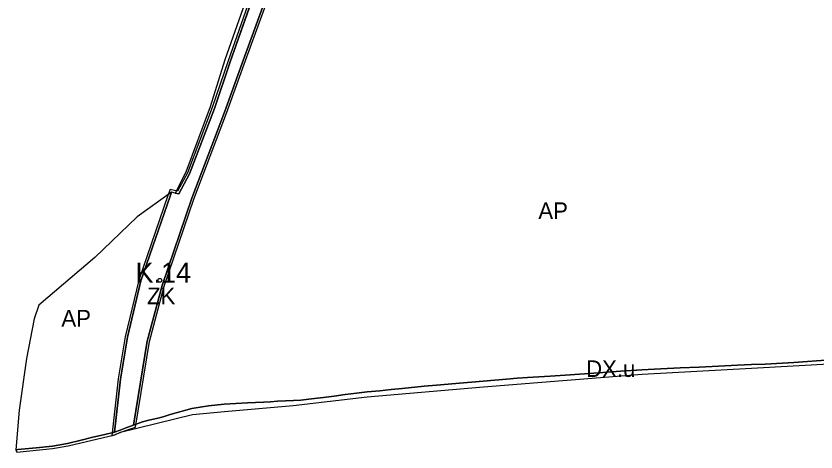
# Model space of a CAD drawing. Extents: x -555509 to -553005, y -1186756 to -1182560.
# Drawn here: x -555509 to -554833, y -1186742 to -1186374 of the extents above; entities that cross this region are included whole.
import ezdxf

# ---------------------------------------------------------------- set-up
doc = ezdxf.new("R2010")
doc.units = 0
for name, color, linetype in [('Level 26', 7, 'Continuous'), ('Level 46', 7, 'Continuous'), ('Level 56', 7, 'Continuous'), ('Level 59', 7, 'Continuous'), ('Level 63', 7, 'Continuous'), ('navrh_ZK', 7, 'Continuous'), ('OBRYS_PLOCH', 7, 'Continuous'), ('stav_AP', 7, 'Continuous'), ('stav_ZK', 7, 'Continuous')]:
    doc.layers.add(name, color=color, linetype=linetype)

msp = doc.modelspace()

# ---------------------------------------------------------------- linework, layer by layer
at = {"layer": 'Level 26'}
for p, q in [((-554821.37, -1186664.53), (-554852.05, -1186666.72)), ((-554964.32, -1186672), (-554980.48, -1186672.71)), ((-554980.05, -1186676.42), (-554887.97, -1186671.38)), ((-554948.16, -1186671.3), (-554964.32, -1186672)), ((-554931.94, -1186670.47), (-554948.16, -1186671.3)), ((-554915.74, -1186669.71), (-554931.94, -1186670.47)), ((-554899.7, -1186668.99), (-554915.74, -1186669.71)), ((-554888, -1186668.27), (-554899.7, -1186668.99)), ((-554876.21, -1186667.95), (-554888, -1186668.27)), ((-554887.97, -1186671.38), (-554789.24, -1186666.07)), ((-554852.05, -1186666.72), (-554876.21, -1186667.95)), ((-555114.15, -1186687.17), (-554980.05, -1186676.42)), ((-555067.42, -1186678.67), (-555076.94, -1186679.25)), ((-555057.9, -1186678.08), (-555067.42, -1186678.67)), ((-555049.48, -1186677.57), (-555057.9, -1186678.08)), ((-555041.02, -1186677.02), (-555049.48, -1186677.57)), ((-555020.94, -1186675.71), (-555041.02, -1186677.02)), ((-555009.68, -1186674.81), (-555020.94, -1186675.71)), ((-554998.42, -1186674.02), (-555009.68, -1186674.81)), ((-554989.46, -1186673.38), (-554998.42, -1186674.02)), ((-554980.48, -1186672.71), (-554989.46, -1186673.38)), ((-555153.89, -1186685.76), (-555164.16, -1186686.63)), ((-555144.04, -1186684.95), (-555153.89, -1186685.76)), ((-555134.47, -1186684.09), (-555144.04, -1186684.95)), ((-555124.31, -1186683.29), (-555134.47, -1186684.09)), ((-555114.3, -1186682.43), (-555124.31, -1186683.29)), ((-555104.56, -1186681.62), (-555114.3, -1186682.43)), ((-555094.73, -1186680.71), (-555104.56, -1186681.62)), ((-555085.82, -1186679.98), (-555094.73, -1186680.71)), ((-555076.94, -1186679.25), (-555085.82, -1186679.98)), ((-555221.37, -1186692.63), (-555230.77, -1186693.78)), ((-555212.22, -1186691.51), (-555221.37, -1186692.63)), ((-555212.22, -1186695.72), (-555114.15, -1186687.17)), ((-555201.78, -1186690.46), (-555212.22, -1186691.51)), ((-555192.13, -1186689.51), (-555201.78, -1186690.46)), ((-555182.72, -1186688.55), (-555192.13, -1186689.51)), ((-555164.16, -1186686.63), (-555182.72, -1186688.55)), ((-555287.89, -1186699.41), (-555293.8, -1186699.81)), ((-555274.43, -1186698.75), (-555287.89, -1186699.41)), ((-555274.79, -1186703.08), (-555212.22, -1186695.72)), ((-555268.4, -1186698.44), (-555274.43, -1186698.75)), ((-555259.21, -1186697.4), (-555268.4, -1186698.44)), ((-555249.31, -1186696.1), (-555259.21, -1186697.4)), ((-555240.22, -1186694.96), (-555249.31, -1186696.1)), ((-555230.77, -1186693.78), (-555240.22, -1186694.96)), ((-555360.21, -1186705.63), (-555378.64, -1186710.67)), ((-555346.28, -1186703.12), (-555360.21, -1186705.63)), ((-555333.11, -1186701.97), (-555346.28, -1186703.12)), ((-555313.32, -1186700.71), (-555333.11, -1186701.97)), ((-555332.83, -1186708.02), (-555274.79, -1186703.08)), ((-555299.97, -1186700.15), (-555313.32, -1186700.71)), ((-555293.8, -1186699.81), (-555299.97, -1186700.15)), ((-555420.67, -1186725.59), (-555359.65, -1186710.58)), ((-555382.98, -1186711.99), (-555387.77, -1186713.28)), ((-555378.64, -1186710.67), (-555382.98, -1186711.99)), ((-555359.65, -1186710.58), (-555332.83, -1186708.02)), ((-555409.6, -1186719.66), (-555415.22, -1186721.67)), ((-555401.91, -1186716.89), (-555409.6, -1186719.66)), ((-555396.64, -1186715.38), (-555401.91, -1186716.89)), ((-555387.77, -1186713.28), (-555396.64, -1186715.38)), ((-555425.54, -1186725.43), (-555434.79, -1186727.67)), ((-555420.84, -1186723.67), (-555425.54, -1186725.43)), ((-555425.26, -1186727.65), (-555420.67, -1186725.59)), ((-555415.22, -1186721.67), (-555420.84, -1186723.67)), ((-555453.9, -1186732.33), (-555465.17, -1186734.97)), ((-555464.81, -1186736.96), (-555425.26, -1186727.65)), ((-555443.89, -1186729.83), (-555453.9, -1186732.33)), ((-555434.79, -1186727.67), (-555443.89, -1186729.83)), ((-555508.02, -1186742.24), (-555477.93, -1186739.2)), ((-555491.66, -1186738.63), (-555507.27, -1186740.17)), ((-555477.98, -1186737.17), (-555491.66, -1186738.63)), ((-555465.17, -1186734.97), (-555477.98, -1186737.17)), ((-555477.93, -1186739.2), (-555464.81, -1186736.96)), ((-555507.27, -1186740.17), (-555508.78, -1186740.27)), ((-555508.78, -1186740.27), (-555508.02, -1186742.24))]:
    msp.add_line(p, q, dxfattribs=at)
at = {"layer": 'Level 46'}
msp.add_circle((-555387.38, -1186597.24), 1.64, dxfattribs=at)
at = {"layer": 'Level 56'}
msp.add_lwpolyline([(-555294.24, -1186306.8), (-555307.65, -1186349.22), (-555329.75, -1186411.97), (-555343.2, -1186451.41), (-555364.14, -1186506.51), (-555372.32, -1186521.97), (-555378.67, -1186520.61), (-555380.64, -1186525.52), (-555405.22, -1186597.12), (-555416.59, -1186645), (-555422.51, -1186680.5), (-555427.89, -1186728.45), (-555420.15, -1186725.55), (-555414.55, -1186723.55), (-555407.81, -1186721.15), (-555396.12, -1186649.06), (-555383.61, -1186602.23), (-555358.59, -1186528.67), (-555330.99, -1186456.07), (-555316.07, -1186414.65), (-555278.64, -1186312.12)], close=True, dxfattribs=at)
at = {"layer": 'navrh_ZK'}
for p, q in [((-555305.75, -1186349.85), (-555327.86, -1186412.63)), ((-555327.86, -1186412.63), (-555341.32, -1186452.09)), ((-555341.32, -1186452.09), (-555362.31, -1186507.34)), ((-555362.31, -1186507.34), (-555371.26, -1186524.24)), ((-555371.26, -1186524.24), (-555374.35, -1186523.58)), ((-555415.22, -1186721.67), (-555409.6, -1186719.66)), ((-555420.84, -1186723.67), (-555415.22, -1186721.67))]:
    msp.add_line(p, q, dxfattribs=at)
for points in [[(-555409.6, -1186719.66), (-555398.08, -1186648.64), (-555385.52, -1186601.65), (-555360.47, -1186527.99), (-555332.87, -1186455.38), (-555317.95, -1186413.97), (-555281.22, -1186313.35)], [(-555374.35, -1186523.58), (-555377.44, -1186522.92), (-555378.76, -1186526.22), (-555403.3, -1186597.68)], [(-555403.3, -1186597.68), (-555414.63, -1186645.4), (-555420.53, -1186680.78), (-555425.54, -1186725.43), (-555420.84, -1186723.67)]]:
    msp.add_lwpolyline(points, dxfattribs=at)
at = {"layer": 'OBRYS_PLOCH'}
for p, q in [((-555281.22, -1186313.35), (-555317.95, -1186413.97)), ((-555310.66, -1186348.84), (-555332.46, -1186411.11)), ((-555327.86, -1186412.63), (-555305.75, -1186349.85)), ((-555305.75, -1186349.85), (-555327.86, -1186412.63)), ((-555332.46, -1186411.11), (-555344.77, -1186450.74)), ((-555341.32, -1186452.09), (-555327.86, -1186412.63)), ((-555327.86, -1186412.63), (-555341.32, -1186452.09)), ((-555317.95, -1186413.97), (-555332.87, -1186455.38)), ((-555344.77, -1186450.74), (-555365.28, -1186506.04)), ((-555362.31, -1186507.34), (-555341.32, -1186452.09)), ((-555341.32, -1186452.09), (-555362.31, -1186507.34)), ((-555332.87, -1186455.38), (-555360.47, -1186527.99)), ((-555365.28, -1186506.04), (-555374.35, -1186523.58)), ((-555371.26, -1186524.24), (-555362.31, -1186507.34)), ((-555362.31, -1186507.34), (-555371.26, -1186524.24)), ((-555374.35, -1186523.58), (-555371.26, -1186524.24)), ((-555371.26, -1186524.24), (-555374.35, -1186523.58)), ((-555360.47, -1186527.99), (-555385.52, -1186601.65)), ((-555385.52, -1186601.65), (-555398.08, -1186648.64)), ((-555398.08, -1186648.64), (-555409.6, -1186719.66)), ((-554852.05, -1186666.72), (-554821.37, -1186664.53)), ((-554821.37, -1186664.53), (-554852.05, -1186666.72)), ((-554980.48, -1186672.71), (-554964.32, -1186672)), ((-554964.32, -1186672), (-554980.48, -1186672.71)), ((-554980.05, -1186676.42), (-554887.97, -1186671.38)), ((-554964.32, -1186672), (-554948.16, -1186671.3)), ((-554948.16, -1186671.3), (-554964.32, -1186672)), ((-554948.16, -1186671.3), (-554931.94, -1186670.47)), ((-554931.94, -1186670.47), (-554948.16, -1186671.3)), ((-554931.94, -1186670.47), (-554915.74, -1186669.71)), ((-554915.74, -1186669.71), (-554931.94, -1186670.47)), ((-554915.74, -1186669.71), (-554899.7, -1186668.99)), ((-554899.7, -1186668.99), (-554915.74, -1186669.71)), ((-554899.7, -1186668.99), (-554888, -1186668.27)), ((-554888, -1186668.27), (-554899.7, -1186668.99)), ((-554888, -1186668.27), (-554876.21, -1186667.95)), ((-554876.21, -1186667.95), (-554888, -1186668.27)), ((-554887.97, -1186671.38), (-554789.24, -1186666.07)), ((-554876.21, -1186667.95), (-554852.05, -1186666.72)), ((-554852.05, -1186666.72), (-554876.21, -1186667.95)), ((-555114.15, -1186687.17), (-554980.05, -1186676.42)), ((-555076.94, -1186679.25), (-555067.42, -1186678.67)), ((-555067.42, -1186678.67), (-555076.94, -1186679.25)), ((-555067.42, -1186678.67), (-555057.9, -1186678.08)), ((-555057.9, -1186678.08), (-555067.42, -1186678.67)), ((-555057.9, -1186678.08), (-555049.48, -1186677.57)), ((-555049.48, -1186677.57), (-555057.9, -1186678.08)), ((-555049.48, -1186677.57), (-555041.02, -1186677.02)), ((-555041.02, -1186677.02), (-555049.48, -1186677.57)), ((-555041.02, -1186677.02), (-555020.94, -1186675.71)), ((-555020.94, -1186675.71), (-555041.02, -1186677.02)), ((-555020.94, -1186675.71), (-555009.68, -1186674.81)), ((-555009.68, -1186674.81), (-555020.94, -1186675.71)), ((-555009.68, -1186674.81), (-554998.42, -1186674.02)), ((-554998.42, -1186674.02), (-555009.68, -1186674.81)), ((-554998.42, -1186674.02), (-554989.46, -1186673.38)), ((-554989.46, -1186673.38), (-554998.42, -1186674.02)), ((-554989.46, -1186673.38), (-554980.48, -1186672.71)), ((-554980.48, -1186672.71), (-554989.46, -1186673.38)), ((-555164.16, -1186686.63), (-555153.89, -1186685.76)), ((-555153.89, -1186685.76), (-555164.16, -1186686.63)), ((-555153.89, -1186685.76), (-555144.04, -1186684.95)), ((-555144.04, -1186684.95), (-555153.89, -1186685.76)), ((-555144.04, -1186684.95), (-555134.47, -1186684.09)), ((-555134.47, -1186684.09), (-555144.04, -1186684.95)), ((-555134.47, -1186684.09), (-555124.31, -1186683.29)), ((-555124.31, -1186683.29), (-555134.47, -1186684.09)), ((-555124.31, -1186683.29), (-555114.3, -1186682.43)), ((-555114.3, -1186682.43), (-555124.31, -1186683.29)), ((-555114.3, -1186682.43), (-555104.56, -1186681.62)), ((-555104.56, -1186681.62), (-555114.3, -1186682.43)), ((-555104.56, -1186681.62), (-555094.73, -1186680.71)), ((-555094.73, -1186680.71), (-555104.56, -1186681.62)), ((-555094.73, -1186680.71), (-555085.82, -1186679.98)), ((-555085.82, -1186679.98), (-555094.73, -1186680.71)), ((-555085.82, -1186679.98), (-555076.94, -1186679.25)), ((-555076.94, -1186679.25), (-555085.82, -1186679.98)), ((-555230.77, -1186693.78), (-555221.37, -1186692.63)), ((-555221.37, -1186692.63), (-555230.77, -1186693.78)), ((-555221.37, -1186692.63), (-555212.22, -1186691.51)), ((-555212.22, -1186691.51), (-555221.37, -1186692.63)), ((-555212.22, -1186695.72), (-555114.15, -1186687.17)), ((-555212.22, -1186691.51), (-555201.78, -1186690.46)), ((-555201.78, -1186690.46), (-555212.22, -1186691.51)), ((-555201.78, -1186690.46), (-555192.13, -1186689.51)), ((-555192.13, -1186689.51), (-555201.78, -1186690.46)), ((-555192.13, -1186689.51), (-555182.72, -1186688.55)), ((-555182.72, -1186688.55), (-555192.13, -1186689.51)), ((-555182.72, -1186688.55), (-555164.16, -1186686.63)), ((-555164.16, -1186686.63), (-555182.72, -1186688.55)), ((-555293.8, -1186699.81), (-555287.89, -1186699.41)), ((-555287.89, -1186699.41), (-555293.8, -1186699.81)), ((-555287.89, -1186699.41), (-555274.43, -1186698.75)), ((-555274.43, -1186698.75), (-555287.89, -1186699.41)), ((-555274.79, -1186703.08), (-555212.22, -1186695.72)), ((-555274.43, -1186698.75), (-555268.4, -1186698.44)), ((-555268.4, -1186698.44), (-555274.43, -1186698.75)), ((-555268.4, -1186698.44), (-555259.21, -1186697.4)), ((-555259.21, -1186697.4), (-555268.4, -1186698.44)), ((-555259.21, -1186697.4), (-555249.31, -1186696.1)), ((-555249.31, -1186696.1), (-555259.21, -1186697.4)), ((-555249.31, -1186696.1), (-555240.22, -1186694.96)), ((-555240.22, -1186694.96), (-555249.31, -1186696.1)), ((-555240.22, -1186694.96), (-555230.77, -1186693.78)), ((-555230.77, -1186693.78), (-555240.22, -1186694.96)), ((-555378.64, -1186710.67), (-555360.21, -1186705.63)), ((-555360.21, -1186705.63), (-555378.64, -1186710.67)), ((-555360.21, -1186705.63), (-555346.28, -1186703.12)), ((-555346.28, -1186703.12), (-555360.21, -1186705.63)), ((-555346.28, -1186703.12), (-555333.11, -1186701.97)), ((-555333.11, -1186701.97), (-555346.28, -1186703.12)), ((-555333.11, -1186701.97), (-555313.32, -1186700.71)), ((-555313.32, -1186700.71), (-555333.11, -1186701.97)), ((-555332.83, -1186708.02), (-555274.79, -1186703.08)), ((-555313.32, -1186700.71), (-555299.97, -1186700.15)), ((-555299.97, -1186700.15), (-555313.32, -1186700.71)), ((-555299.97, -1186700.15), (-555293.8, -1186699.81)), ((-555293.8, -1186699.81), (-555299.97, -1186700.15)), ((-555420.67, -1186725.59), (-555359.65, -1186710.58)), ((-555387.77, -1186713.28), (-555382.98, -1186711.99)), ((-555382.98, -1186711.99), (-555387.77, -1186713.28)), ((-555382.98, -1186711.99), (-555378.64, -1186710.67)), ((-555378.64, -1186710.67), (-555382.98, -1186711.99)), ((-555359.65, -1186710.58), (-555332.83, -1186708.02)), ((-555415.22, -1186721.67), (-555409.6, -1186719.66)), ((-555409.6, -1186719.66), (-555415.22, -1186721.67)), ((-555409.6, -1186719.66), (-555401.91, -1186716.89)), ((-555401.91, -1186716.89), (-555409.6, -1186719.66)), ((-555401.91, -1186716.89), (-555396.64, -1186715.38)), ((-555396.64, -1186715.38), (-555401.91, -1186716.89)), ((-555396.64, -1186715.38), (-555387.77, -1186713.28)), ((-555387.77, -1186713.28), (-555396.64, -1186715.38)), ((-555425.54, -1186725.43), (-555434.79, -1186727.67)), ((-555420.84, -1186723.67), (-555425.54, -1186725.43)), ((-555425.26, -1186727.65), (-555420.67, -1186725.59)), ((-555420.84, -1186723.67), (-555415.22, -1186721.67)), ((-555415.22, -1186721.67), (-555420.84, -1186723.67)), ((-555453.9, -1186732.33), (-555465.17, -1186734.97)), ((-555464.81, -1186736.96), (-555425.26, -1186727.65)), ((-555443.89, -1186729.83), (-555453.9, -1186732.33)), ((-555434.79, -1186727.67), (-555443.89, -1186729.83)), ((-555508.02, -1186742.24), (-555477.93, -1186739.2)), ((-555491.66, -1186738.63), (-555507.27, -1186740.17)), ((-555477.98, -1186737.17), (-555491.66, -1186738.63)), ((-555465.17, -1186734.97), (-555477.98, -1186737.17)), ((-555477.93, -1186739.2), (-555464.81, -1186736.96)), ((-555507.27, -1186740.17), (-555508.78, -1186740.27)), ((-555508.78, -1186740.27), (-555508.02, -1186742.24))]:
    msp.add_line(p, q, dxfattribs=at)
for points in [[(-555409.6, -1186719.66), (-555398.08, -1186648.64), (-555385.52, -1186601.65), (-555360.47, -1186527.99), (-555332.87, -1186455.38), (-555317.95, -1186413.97), (-555281.22, -1186313.35)], [(-555374.35, -1186523.58), (-555377.44, -1186522.92), (-555378.76, -1186526.22), (-555403.3, -1186597.68)], [(-555403.3, -1186597.68), (-555414.63, -1186645.4), (-555420.53, -1186680.78), (-555425.54, -1186725.43), (-555420.84, -1186723.67)]]:
    msp.add_lwpolyline(points, dxfattribs=at)
at = {"layer": 'stav_AP'}
for p, q in [((-555281.22, -1186313.35), (-555317.95, -1186413.97)), ((-555317.95, -1186413.97), (-555332.87, -1186455.38)), ((-555332.87, -1186455.38), (-555360.47, -1186527.99)), ((-555377.44, -1186522.92), (-555406.59, -1186543.53)), ((-555360.47, -1186527.99), (-555385.52, -1186601.65)), ((-555385.52, -1186601.65), (-555398.08, -1186648.64)), ((-555398.08, -1186648.64), (-555409.6, -1186719.66)), ((-554852.05, -1186666.72), (-554821.37, -1186664.53)), ((-554980.48, -1186672.71), (-554964.32, -1186672)), ((-554964.32, -1186672), (-554948.16, -1186671.3)), ((-554948.16, -1186671.3), (-554931.94, -1186670.47)), ((-554931.94, -1186670.47), (-554915.74, -1186669.71)), ((-554915.74, -1186669.71), (-554899.7, -1186668.99)), ((-554899.7, -1186668.99), (-554888, -1186668.27)), ((-554888, -1186668.27), (-554876.21, -1186667.95)), ((-554876.21, -1186667.95), (-554852.05, -1186666.72)), ((-555076.94, -1186679.25), (-555067.42, -1186678.67)), ((-555067.42, -1186678.67), (-555057.9, -1186678.08)), ((-555057.9, -1186678.08), (-555049.48, -1186677.57)), ((-555049.48, -1186677.57), (-555041.02, -1186677.02)), ((-555041.02, -1186677.02), (-555020.94, -1186675.71)), ((-555020.94, -1186675.71), (-555009.68, -1186674.81)), ((-555009.68, -1186674.81), (-554998.42, -1186674.02)), ((-554998.42, -1186674.02), (-554989.46, -1186673.38)), ((-554989.46, -1186673.38), (-554980.48, -1186672.71)), ((-555164.16, -1186686.63), (-555153.89, -1186685.76)), ((-555153.89, -1186685.76), (-555144.04, -1186684.95)), ((-555144.04, -1186684.95), (-555134.47, -1186684.09)), ((-555134.47, -1186684.09), (-555124.31, -1186683.29)), ((-555124.31, -1186683.29), (-555114.3, -1186682.43)), ((-555114.3, -1186682.43), (-555104.56, -1186681.62)), ((-555104.56, -1186681.62), (-555094.73, -1186680.71)), ((-555094.73, -1186680.71), (-555085.82, -1186679.98)), ((-555085.82, -1186679.98), (-555076.94, -1186679.25)), ((-555230.77, -1186693.78), (-555221.37, -1186692.63)), ((-555221.37, -1186692.63), (-555212.22, -1186691.51)), ((-555212.22, -1186691.51), (-555201.78, -1186690.46)), ((-555201.78, -1186690.46), (-555192.13, -1186689.51)), ((-555192.13, -1186689.51), (-555182.72, -1186688.55)), ((-555182.72, -1186688.55), (-555164.16, -1186686.63)), ((-555293.8, -1186699.81), (-555287.89, -1186699.41)), ((-555287.89, -1186699.41), (-555274.43, -1186698.75)), ((-555274.43, -1186698.75), (-555268.4, -1186698.44)), ((-555268.4, -1186698.44), (-555259.21, -1186697.4)), ((-555259.21, -1186697.4), (-555249.31, -1186696.1)), ((-555249.31, -1186696.1), (-555240.22, -1186694.96)), ((-555240.22, -1186694.96), (-555230.77, -1186693.78)), ((-555378.64, -1186710.67), (-555360.21, -1186705.63)), ((-555360.21, -1186705.63), (-555346.28, -1186703.12)), ((-555346.28, -1186703.12), (-555333.11, -1186701.97)), ((-555333.11, -1186701.97), (-555313.32, -1186700.71)), ((-555313.32, -1186700.71), (-555299.97, -1186700.15)), ((-555299.97, -1186700.15), (-555293.8, -1186699.81)), ((-555506.13, -1186707.01), (-555508.78, -1186740.27)), ((-555387.77, -1186713.28), (-555382.98, -1186711.99)), ((-555382.98, -1186711.99), (-555378.64, -1186710.67)), ((-555409.6, -1186719.66), (-555401.91, -1186716.89)), ((-555401.91, -1186716.89), (-555396.64, -1186715.38)), ((-555396.64, -1186715.38), (-555387.77, -1186713.28)), ((-555434.79, -1186727.67), (-555425.54, -1186725.43)), ((-555465.17, -1186734.97), (-555453.9, -1186732.33)), ((-555453.9, -1186732.33), (-555443.89, -1186729.83)), ((-555443.89, -1186729.83), (-555434.79, -1186727.67)), ((-555507.27, -1186740.17), (-555491.66, -1186738.63)), ((-555491.66, -1186738.63), (-555477.98, -1186737.17)), ((-555477.98, -1186737.17), (-555465.17, -1186734.97)), ((-555508.78, -1186740.27), (-555507.27, -1186740.17))]:
    msp.add_line(p, q, dxfattribs=at)
for points in [[(-555403.3, -1186597.68), (-555378.76, -1186526.22), (-555377.44, -1186522.92)], [(-555406.59, -1186543.53), (-555442.31, -1186577.98), (-555489.54, -1186618.27), (-555493.41, -1186629.7), (-555499.91, -1186663.18), (-555506.13, -1186707.01)], [(-555425.54, -1186725.43), (-555420.53, -1186680.78), (-555414.63, -1186645.4), (-555403.3, -1186597.68)]]:
    msp.add_lwpolyline(points, dxfattribs=at)
at = {"layer": 'stav_ZK'}
for p, q in [((-555310.66, -1186348.84), (-555332.46, -1186411.11)), ((-555327.86, -1186412.63), (-555305.75, -1186349.85)), ((-555332.46, -1186411.11), (-555344.77, -1186450.74)), ((-555341.32, -1186452.09), (-555327.86, -1186412.63)), ((-555344.77, -1186450.74), (-555365.28, -1186506.04)), ((-555362.31, -1186507.34), (-555341.32, -1186452.09)), ((-555365.28, -1186506.04), (-555374.35, -1186523.58)), ((-555371.26, -1186524.24), (-555362.31, -1186507.34)), ((-555374.35, -1186523.58), (-555371.26, -1186524.24))]:
    msp.add_line(p, q, dxfattribs=at)

# ---------------------------------------------------------------- texts
at = {"layer": 'Level 46'}
msp.add_text('K.14', height=17, dxfattribs=at).set_placement((-555407.83, -1186599.27))
at = {"layer": 'Level 59'}
for s, p in [('AP', (-555067.84, -1186545.45)), ('AP', (-555470.48, -1186636.27)), ('DX.u', (-555027.55, -1186678.85))]:
    msp.add_text(s, height=14, dxfattribs=at).set_placement(p)
at = {"layer": 'Level 63'}
msp.add_text('ZK', height=14, dxfattribs=at).set_placement((-555398.17, -1186617.42))

doc.saveas('drawing.dxf')
